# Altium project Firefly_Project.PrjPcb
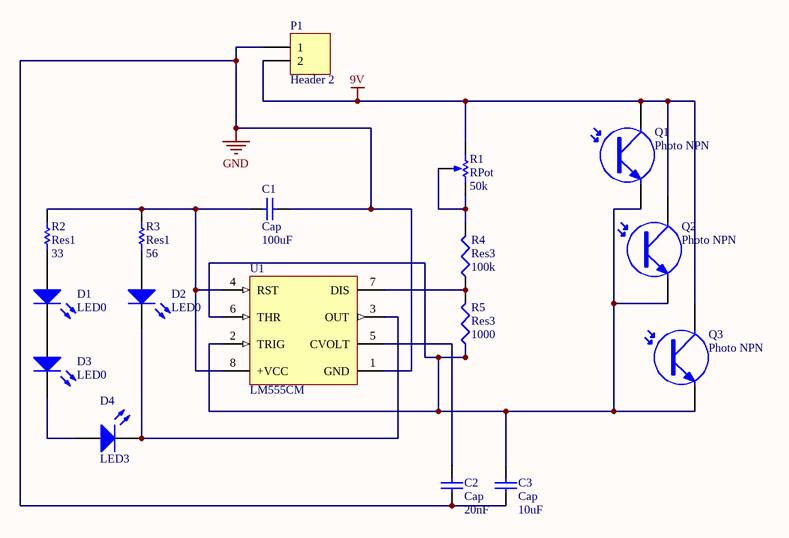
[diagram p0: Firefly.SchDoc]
1 sheet, 17 parts. Net scope: global (net labels, ports and power ports of the same name join across sheets).
Board file: firefly.PcbDoc

## Sheet Firefly.SchDoc
size A

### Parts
C1  Cap  value 100uF  [RAD-0.3]
C2  Cap  value 20nF  [C1206]
C3  Cap  value 10uF  [C1206]
D1  LED0  [LED-0]
D2  LED0  [LED-0]
D3  LED0  [LED-0]
D4  LED3  [3.5X2.8X1.9]
P1  Header 2  [HDR1X2]
Q1  Photo NPN  [LED-0]
Q2  Photo NPN  [LED-0]
Q3  Photo NPN  [LED-0]
R1  RPot  value 50k  [VR5]
R2  Res1  value 33  [AXIAL-0.3]
R3  Res1  value 56  [AXIAL-0.3]
R4  Res3  value 100k  [C1206]
R5  Res3  value 1000  [C1206]
U1  LM555CM  [M08A_N]

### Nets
9V: P1.2 Q1.1(C) Q2.1(C) Q3.1(C) R1.1(TOP)
GND: C1.1 C2.1 C3.1 P1.1 U1.1(GND)
NetC1_2: C1.2 R2.2 R3.2 U1.4(RST) U1.8(+VCC)
NetC2_2: C2.2 U1.5(CVOLT)
NetC3_2: C3.2 Q1.3(E) Q2.3(E) Q3.3(E) R5.1 U1.2(TRIG) U1.6(THR)
NetD1_1: D1.1(A) R2.1
NetD1_2: D1.2(K) D3.1(A)
NetD2_1: D2.1(A) R3.1
NetD2_2: D2.2(K) D4.2(K) U1.3(OUT)
NetD3_2: D3.2(K) D4.1(A)
NetR1_2: R1.2(BOT) R1.3(TAP) R4.2
NetR4_1: R4.1 R5.2 U1.7(DIS)

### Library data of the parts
C1-C3 = Cap: Capacitor
D1-D3 = LED0: Typical INFRARED GaAs LED
D4 = LED3: Typical BLUE SiC LED
P1 = Header 2: Header, 2-Pin
Q1-Q3 = Photo NPN: NPN Phototransistor
R1 = RPot: Potentiometer; Sim Note: Enter the Resistance value and the set point into parameter fields.; Set Position: 0.5
R2 R3 = Res1: Resistor
R4 R5 = Res3: Resistor
U1 = LM555CM: Timer, 8-pin Narrow SOIC; Manufacturer: National Semiconductor; PackageTopMarking: NSZXTT*LM*555CM; PowerWise: N; CompType: Analog IC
